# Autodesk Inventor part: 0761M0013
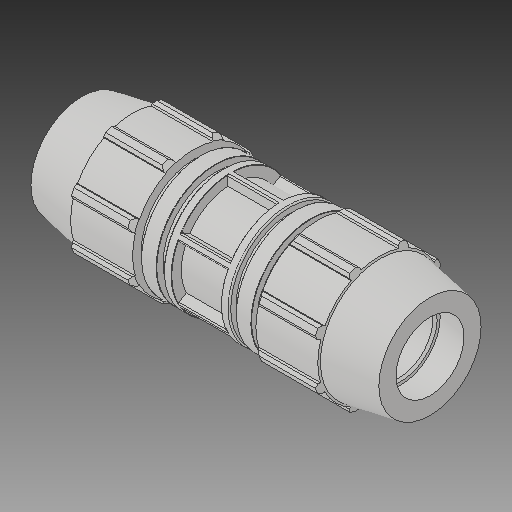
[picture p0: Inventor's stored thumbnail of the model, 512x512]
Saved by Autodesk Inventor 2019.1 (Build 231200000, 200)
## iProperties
Created: 2017-02
Part Number: 0761M0013
Material: Generic
Description: PLASSON REPAIR COUPLER 1 1/4'' - 1 1/4''
Document SubType Name: Modeling
Designer: KIM
Mass: 2544.89 g
Surface Area: 2949.22 cm^2
Volume: 2544.89 cm^3
Density: 1 g/cm^3
Appearance: Default
Author: KIM
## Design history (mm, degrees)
derived "0761M.ipt"
feature "Solid1::0761M.ipt"
tag "TaggingFeature1"
body "Solid1"
other parameters: "d1" = 214.884, "d2" = 42.1, "d4" = 17.907, "d5" = 30.69771, "d7" = 82.042, "d8" = 61.5315, "d9" = 30.69771, "d11" = 9.35567, "d12" = 65.6336, "d13" = 120 deg, "d14" = 63.15, "d15" = 10 deg, "d16" = 73.8378, "d19" = 35 deg, "d20" = 17.5 deg, "d21" = 76.29906, "d23" = 0, "d25" = 360 deg, "d27" = 1.64084, "d33" = 0.2, "d34" = 4.1021, "d36" = 0, "d37" = 0.842, "d38" = 0.842, "d40" = 360 deg, "d42" = 38.67912, "d43" = 2.46126, "d46" = 1.263, "d50" = 4.12218, "d51" = 65.6336, "d52" = 4.12218, "d_" = 42.1, "E_" = 82.042, "H_" = 214.884, "l_" = 86.106, "d49" = 17.60002
